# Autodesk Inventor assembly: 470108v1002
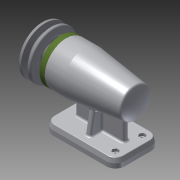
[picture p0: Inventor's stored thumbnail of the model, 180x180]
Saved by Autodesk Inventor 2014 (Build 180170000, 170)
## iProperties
Created: 2017-01
Part Number: 470108v1002
Document SubType Name: Assembly
Designer: user
Author: user
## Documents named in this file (12)
- C:\Users\user\Desktop\470108v1002\470108v1002.iam
- C:\Users\user\Desktop\470108v1002\V벨트풀리.ipt
- C:\Users\user\Desktop\470108v1002\멈춤나사 M3x8.ipt
- C:\Users\user\Desktop\470108v1002\베어링 6004.ipt
- C:\Users\user\Desktop\470108v1002\베어링 51202.ipt
- C:\Users\user\Desktop\470108v1002\본체.ipt
- C:\Users\user\Desktop\470108v1002\볼트 M4 x 12.ipt
- C:\Users\user\Desktop\470108v1002\어댑터슬리브.ipt
- C:\Users\user\Desktop\470108v1002\오일 실.ipt
- C:\Users\user\Desktop\470108v1002\축.ipt
- C:\Users\user\Desktop\470108v1002\커버.ipt
- C:\Users\user\Desktop\470108v1002\키 5 x 5 x 16.ipt
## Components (5 placed, 2 different names)
1. V벨트풀리:1 — Mate:17, Mate:18, Mate:19, Angle:1
2. ISO 4762 M4 x 12:1 — Mate:4, Mate:8
3. ISO 4762 M4 x 12:2 — Mate:6, Mate:9
4. ISO 4762 M4 x 12:3 — Mate:7, Mate:11
5. ISO 4762 M4 x 12:4 — Mate:5, Mate:10
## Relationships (12: Mate 11, Angle 1)
- Mate:4: ISO 4762 M4 x 12:1
- Mate:5: ISO 4762 M4 x 12:4
- Mate:6: ISO 4762 M4 x 12:2
- Mate:7: ISO 4762 M4 x 12:3
- Mate:8: ISO 4762 M4 x 12:1
- Mate:9: ISO 4762 M4 x 12:2
- Mate:10: ISO 4762 M4 x 12:4
- Mate:11: ISO 4762 M4 x 12:3
- Mate:17: V벨트풀리:1
- Mate:18: V벨트풀리:1
- Mate:19: V벨트풀리:1
- Angle:1: V벨트풀리:1
